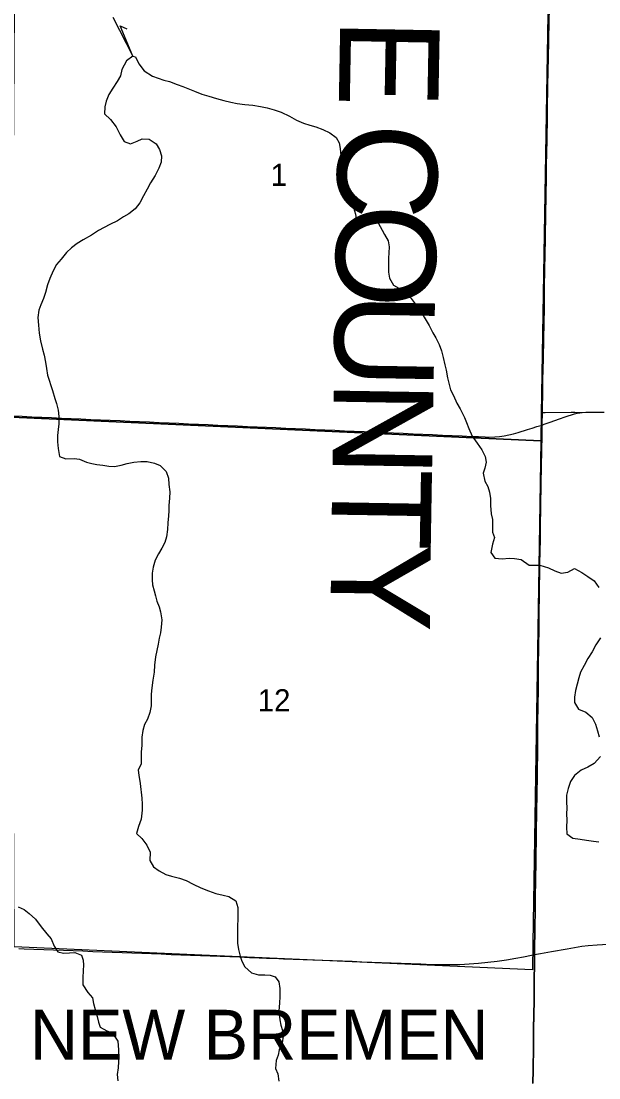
# Model space of a CAD drawing. Extents: x 0 to 34, y 0 to 22.
# Drawn here: x 6.802 to 7.901, y 17.185 to 19.194 of the extents above; entities that cross this region are included whole.
import ezdxf

# ---------------------------------------------------------------- set-up
doc = ezdxf.new("R2010")
doc.units = 0
for name, color, linetype in [('GM_X_Corporation', 7, 'Continuous'), ('GM_X_Corporation_Text', 7, 'Continuous'), ('GM_X_County_Road', 7, 'Continuous'), ('GM_X_County_Text', 7, 'Continuous'), ('GM_X_Minor_River', 7, 'Continuous'), ('GM_X_Section_Text', 7, 'Continuous'), ('GM_X_State_Route', 7, 'Continuous'), ('GM_X_Township_Road', 7, 'Continuous')]:
    doc.layers.add(name, color=color, linetype=linetype)

msp = doc.modelspace()

# ---------------------------------------------------------------- linework, layer by layer
at = {"layer": 'GM_X_Corporation'}
for points in [[(6.7967, 19.4154), (7.8071, 19.3973), (7.7914, 18.4475), (7.7907, 18.396), (6.7843, 18.4413), (6.7907, 19.4159)], [(7.7907, 18.396), (7.7756, 17.4406), (7.775, 17.3902), (6.7891, 17.4339), (6.7843, 18.4413)]]:
    msp.add_lwpolyline(points, close=True, dxfattribs=at)
for points in [[(7.8077, 19.2659), (7.8062, 19.1933), (7.8046, 19.1231), (7.8042, 19.1001), (7.8035, 19.0709), (7.803, 19.0255), (7.8028, 19.0087), (7.802, 18.9714), (7.8013, 18.9404), (7.8009, 18.923), (7.8007, 18.9013), (7.8002, 18.8578), (7.7997, 18.8304), (7.7991, 18.7813), (7.7984, 18.7484), (7.798, 18.7254), (7.7973, 18.6856), (7.7968, 18.6484), (7.7958, 18.5906), (7.7951, 18.552), (7.7941, 18.5123), (7.7937, 18.4937), (7.7933, 18.4506), (7.7929, 18.4266), (7.7926, 18.406), (7.792, 18.3768), (7.7914, 18.3476), (7.7909, 18.3147), (7.7902, 18.2712), (7.7895, 18.2321), (7.7892, 18.2091), (7.7888, 18.1855), (7.7885, 18.1637), (7.788, 18.1426), (7.7876, 18.1196), (7.7874, 18.0979), (7.7872, 18.0736), (7.787, 18.0631), (7.7867, 18.0339), (7.7864, 18.0109), (7.7863, 17.9991), (7.7859, 17.973), (7.7857, 17.9519), (7.7854, 17.9164), (7.7853, 17.8996), (7.7847, 17.8518), (7.7844, 17.8083), (7.784, 17.7648), (7.7832, 17.7188), (7.7828, 17.6971), (7.782, 17.648), (7.7814, 17.5977), (7.7808, 17.5616), (7.7801, 17.5281), (7.7799, 17.5113), (7.7793, 17.4635), (7.7789, 17.4324), (7.7787, 17.4202), (7.7785, 17.4094), (7.7785, 17.3964), (7.7783, 17.3759), (7.7781, 17.3547), (7.7779, 17.3342), (7.7775, 17.3032), (7.7771, 17.2808), (7.7767, 17.2454), (7.7759, 17.1994), (7.7755, 17.1752)], [(7.7755, 17.1752), (7.7759, 17.1994), (7.7767, 17.2454), (7.7771, 17.2808), (7.7775, 17.3032), (7.7779, 17.3342), (7.7781, 17.3547), (7.7783, 17.3759), (7.7785, 17.3964), (7.7785, 17.4094), (7.7787, 17.4202), (7.7789, 17.4324), (7.7793, 17.4635), (7.7799, 17.5113), (7.7801, 17.5281), (7.7808, 17.5616), (7.7814, 17.5977), (7.782, 17.648), (7.7828, 17.6971), (7.7832, 17.7188), (7.784, 17.7648), (7.7844, 17.8083), (7.7847, 17.8518), (7.7853, 17.8996), (7.7854, 17.9164), (7.7857, 17.9519), (7.7859, 17.973), (7.7863, 17.9991), (7.7864, 18.0109), (7.7867, 18.0339), (7.787, 18.0631), (7.7872, 18.0736), (7.7874, 18.0979), (7.7876, 18.1196), (7.788, 18.1426), (7.7885, 18.1637), (7.7888, 18.1855), (7.7892, 18.2091), (7.7895, 18.2321), (7.7902, 18.2712), (7.7909, 18.3147), (7.7914, 18.3476), (7.792, 18.3768), (7.7926, 18.406), (7.7929, 18.4266), (7.7933, 18.4506), (7.7937, 18.4937), (7.7941, 18.5123), (7.7951, 18.552), (7.7958, 18.5906), (7.7968, 18.6484), (7.7973, 18.6856), (7.798, 18.7254), (7.7984, 18.7484), (7.7991, 18.7813), (7.7997, 18.8304), (7.8002, 18.8578), (7.8007, 18.9013), (7.8009, 18.923), (7.8013, 18.9404), (7.802, 18.9714), (7.8028, 19.0087), (7.803, 19.0255), (7.8035, 19.0709), (7.8042, 19.1001), (7.8046, 19.1231), (7.8062, 19.1933), (7.8077, 19.2659)], [(7.7755, 17.1752), (7.7759, 17.1994), (7.7767, 17.2454), (7.7771, 17.2808), (7.7775, 17.3032), (7.7779, 17.3342), (7.7781, 17.3547), (7.7783, 17.3759), (7.7785, 17.3964), (7.7785, 17.4094), (7.7787, 17.4202), (7.7789, 17.4324), (7.7793, 17.4635), (7.7799, 17.5113), (7.7801, 17.5281), (7.7808, 17.5616), (7.7814, 17.5977), (7.782, 17.648), (7.7828, 17.6971), (7.7832, 17.7188), (7.784, 17.7648), (7.7844, 17.8083), (7.7847, 17.8518), (7.7853, 17.8996), (7.7854, 17.9164), (7.7857, 17.9519), (7.7859, 17.973), (7.7863, 17.9991), (7.7864, 18.0109), (7.7867, 18.0339), (7.787, 18.0631), (7.7872, 18.0736), (7.7874, 18.0979), (7.7876, 18.1196), (7.788, 18.1426), (7.7885, 18.1637), (7.7888, 18.1855), (7.7892, 18.2091), (7.7895, 18.2321), (7.7902, 18.2712), (7.7909, 18.3147), (7.7914, 18.3476), (7.792, 18.3768), (7.7926, 18.406), (7.7929, 18.4266), (7.7933, 18.4506), (7.7937, 18.4937), (7.7941, 18.5123), (7.7951, 18.552), (7.7958, 18.5906), (7.7968, 18.6484), (7.7973, 18.6856), (7.798, 18.7254), (7.7984, 18.7484), (7.7991, 18.7813), (7.7997, 18.8304), (7.8002, 18.8578), (7.8007, 18.9013), (7.8009, 18.923), (7.8013, 18.9404), (7.802, 18.9714), (7.8028, 19.0087), (7.803, 19.0255), (7.8035, 19.0709), (7.8042, 19.1001), (7.8046, 19.1231), (7.8062, 19.1933), (7.8077, 19.2659)], [(7.8077, 19.2659), (7.8062, 19.1933), (7.8046, 19.1231), (7.8042, 19.1001), (7.8035, 19.0709), (7.803, 19.0255), (7.8028, 19.0087), (7.802, 18.9714), (7.8013, 18.9404), (7.8009, 18.923), (7.8007, 18.9013), (7.8002, 18.8578), (7.7997, 18.8304), (7.7991, 18.7813), (7.7984, 18.7484), (7.798, 18.7254), (7.7973, 18.6856), (7.7968, 18.6484), (7.7958, 18.5906), (7.7951, 18.552), (7.7941, 18.5123), (7.7937, 18.4937), (7.7933, 18.4506), (7.7929, 18.4266), (7.7926, 18.406), (7.792, 18.3768), (7.7914, 18.3476), (7.7909, 18.3147), (7.7902, 18.2712), (7.7895, 18.2321), (7.7892, 18.2091), (7.7888, 18.1855), (7.7885, 18.1637), (7.788, 18.1426), (7.7876, 18.1196), (7.7874, 18.0979), (7.7872, 18.0736), (7.787, 18.0631), (7.7867, 18.0339), (7.7864, 18.0109), (7.7863, 17.9991), (7.7859, 17.973), (7.7857, 17.9519), (7.7854, 17.9164), (7.7853, 17.8996), (7.7847, 17.8518), (7.7844, 17.8083), (7.784, 17.7648), (7.7832, 17.7188), (7.7828, 17.6971), (7.782, 17.648), (7.7814, 17.5977), (7.7808, 17.5616), (7.7801, 17.5281), (7.7799, 17.5113), (7.7793, 17.4635), (7.7789, 17.4324), (7.7787, 17.4202), (7.7785, 17.4094), (7.7785, 17.3964), (7.7783, 17.3759), (7.7781, 17.3547), (7.7779, 17.3342), (7.7775, 17.3032), (7.7771, 17.2808), (7.7767, 17.2454), (7.7759, 17.1994), (7.7755, 17.1752)]]:
    msp.add_lwpolyline(points, dxfattribs=at)
at = {"layer": 'GM_X_County_Road'}
for p, q in [((7.7931, 18.4261), (7.7935, 18.45)), ((7.7788, 17.4008), (7.7789, 17.4196))]:
    msp.add_line(p, q, dxfattribs=at)
for points in [[(7.7935, 18.45), (7.794, 18.4931), (7.7944, 18.5117), (7.7948, 18.5304), (7.7951, 18.5409), (7.7953, 18.5515), (7.7957, 18.5701), (7.7959, 18.5801), (7.7961, 18.59), (7.7967, 18.6273), (7.7968, 18.6376), (7.797, 18.6478), (7.7973, 18.6664), (7.7974, 18.6758), (7.7975, 18.6851), (7.7982, 18.7249), (7.7987, 18.7478), (7.799, 18.7643), (7.7994, 18.7808), (7.7996, 18.7994), (7.7998, 18.8146), (7.8, 18.8299), (7.8004, 18.8572), (7.8009, 18.9007), (7.801, 18.9116), (7.8012, 18.9225), (7.8015, 18.9398), (7.8018, 18.9554), (7.8022, 18.9709), (7.8026, 18.9895), (7.8031, 19.0082), (7.8032, 19.025), (7.8036, 19.057), (7.8038, 19.0703), (7.8044, 19.0995), (7.8046, 19.111), (7.8048, 19.1225), (7.8057, 19.1598), (7.8061, 19.1762), (7.8064, 19.1927), (7.8076, 19.2477)], [(6.7856, 18.4436), (6.8043, 18.4427), (6.8229, 18.4419), (6.8415, 18.4411), (6.8601, 18.4402), (6.8788, 18.4394), (6.8974, 18.4386), (6.916, 18.4377), (6.9346, 18.4369), (6.9532, 18.4361), (6.9719, 18.4352), (6.9905, 18.4344), (7.0091, 18.4336), (7.0277, 18.4327), (7.0464, 18.4319), (7.065, 18.4311), (7.0836, 18.4302), (7.1022, 18.4294), (7.1208, 18.4286), (7.1395, 18.4277), (7.1581, 18.4269), (7.1767, 18.4261), (7.1953, 18.4252), (7.214, 18.4244), (7.2326, 18.4236), (7.2512, 18.4227), (7.2691, 18.4219), (7.287, 18.4211), (7.3057, 18.4203), (7.3243, 18.4195), (7.3429, 18.4187), (7.3615, 18.4178), (7.3801, 18.417), (7.3988, 18.4162), (7.4174, 18.4153), (7.436, 18.4145), (7.4546, 18.4137), (7.4733, 18.4129), (7.4919, 18.412), (7.5105, 18.4112), (7.5291, 18.4104), (7.5477, 18.4096), (7.5664, 18.4087), (7.585, 18.4079), (7.6036, 18.4071), (7.6222, 18.4063), (7.6409, 18.4055), (7.6595, 18.4046), (7.6722, 18.4041), (7.6849, 18.4035), (7.694, 18.4033), (7.703, 18.4036), (7.7121, 18.4043), (7.721, 18.4055), (7.7299, 18.4072), (7.7388, 18.4093), (7.7475, 18.4118), (7.7652, 18.4174), (7.7742, 18.4202), (7.7831, 18.4231), (7.7931, 18.4261)], [(7.7931, 18.4261), (7.7971, 18.4275), (7.8088, 18.4318), (7.8263, 18.4381), (7.8369, 18.4416), (7.8547, 18.4471), (7.86, 18.4485), (7.8648, 18.4494), (7.8661, 18.4496)], [(7.7935, 18.45), (7.7991, 18.4501), (7.8485, 18.4504), (7.8555, 18.4503), (7.8661, 18.4496)], [(7.8661, 18.4496), (7.8691, 18.4501), (7.8765, 18.4506), (7.8876, 18.4508), (7.9112, 18.4508)], [(7.7858, 17.9311), (7.7859, 17.9513), (7.7862, 17.9724), (7.7864, 17.9855), (7.7865, 17.9985), (7.7866, 18.0103), (7.7869, 18.0333), (7.7873, 18.0625), (7.7874, 18.0731), (7.7875, 18.0852), (7.7876, 18.0973), (7.7877, 18.1082), (7.7878, 18.1191), (7.7882, 18.1421), (7.7885, 18.1526), (7.7887, 18.1632), (7.7889, 18.1741), (7.7891, 18.1849), (7.7894, 18.2085), (7.7896, 18.22), (7.7898, 18.2315), (7.7902, 18.2604), (7.7904, 18.2707), (7.7907, 18.2893), (7.7909, 18.3017), (7.7911, 18.3142), (7.7917, 18.3471), (7.7928, 18.4055), (7.793, 18.4158), (7.7931, 18.4261)], [(7.7789, 17.4196), (7.7792, 17.4319), (7.7795, 17.4629), (7.7802, 17.5108), (7.7803, 17.5276), (7.7807, 17.5443), (7.781, 17.5611), (7.7816, 17.5971), (7.7819, 17.6158), (7.7822, 17.6475), (7.783, 17.6965), (7.7833, 17.7074), (7.7835, 17.7183), (7.7838, 17.7369), (7.7842, 17.7643), (7.7844, 17.7829), (7.7847, 17.8078), (7.7848, 17.8264), (7.7848, 17.8389), (7.7852, 17.8699), (7.7856, 17.8991), (7.7857, 17.9159), (7.7858, 17.9311)], [(7.7757, 17.1746), (7.7761, 17.1989), (7.7769, 17.2448), (7.7774, 17.2803), (7.7778, 17.3026), (7.7782, 17.3337), (7.7783, 17.3439), (7.7784, 17.3542), (7.7786, 17.3753), (7.7788, 17.3958), (7.7788, 17.4008)]]:
    msp.add_lwpolyline(points, dxfattribs=at)
at = {"layer": 'GM_X_Minor_River'}
for points in [[(6.9767, 19.2013), (7.0145, 19.1272), (6.9907, 19.185)], [(6.9907, 19.185), (7.0034, 19.179)], [(7.0145, 19.1272), (7.0026, 19.1187), (6.9938, 19.1018), (6.9912, 19.0901), (6.9852, 19.0793), (6.9765, 19.0666), (6.969, 19.0546), (6.9641, 19.0419), (6.9612, 19.0313), (6.9609, 19.018), (6.9723, 19.0067), (6.9833, 18.9928), (6.9905, 18.9778), (6.9985, 18.965), (7.0106, 18.9605), (7.0232, 18.9655), (7.0328, 18.9702), (7.0461, 18.9695), (7.0591, 18.9604), (7.0657, 18.9496), (7.0692, 18.9381), (7.0685, 18.926), (7.0644, 18.9143), (7.0572, 18.9005), (7.0484, 18.8863), (7.0417, 18.8743), (7.0353, 18.8616), (7.0281, 18.8485), (7.0191, 18.8373), (7.0071, 18.8278), (6.997, 18.8216), (6.9858, 18.8143), (6.9712, 18.8071), (6.9605, 18.8017), (6.9493, 18.7959), (6.9362, 18.7871), (6.9204, 18.7784), (6.9088, 18.7711), (6.898, 18.7627), (6.8883, 18.7542), (6.8785, 18.7416), (6.8698, 18.7312), (6.8635, 18.7192), (6.8566, 18.7049), (6.8525, 18.6929), (6.8487, 18.6782), (6.845, 18.6669), (6.8398, 18.6549), (6.8361, 18.6447), (6.8342, 18.6303), (6.8353, 18.6159), (6.8364, 18.6007), (6.8391, 18.5862), (6.8429, 18.5705), (6.846, 18.559), (6.8487, 18.5457), (6.8506, 18.5335), (6.8526, 18.5209), (6.8617, 18.4918), (6.8666, 18.4768), (6.8694, 18.4673), (6.8725, 18.4543), (6.8737, 18.4421), (6.8737, 18.4281), (6.873, 18.4178), (6.8716, 18.4061), (6.8716, 18.3939), (6.8728, 18.3817), (6.8755, 18.3661), (6.8875, 18.3616), (6.9031, 18.3627), (6.9133, 18.3609), (6.9268, 18.3556), (6.9366, 18.3531), (6.9464, 18.3513), (6.9574, 18.3495), (6.9691, 18.3481), (6.9801, 18.3474), (6.9923, 18.3501), (7.0038, 18.3532), (7.0167, 18.3552), (7.03, 18.3567), (7.0422, 18.3568), (7.0561, 18.3538), (7.067, 18.3489), (7.0781, 18.338), (7.0823, 18.325), (7.0835, 18.3128), (7.0854, 18.2994), (7.0847, 18.2869), (7.0832, 18.2729), (7.083, 18.263), (7.0824, 18.2536), (7.0812, 18.2399), (7.0806, 18.2278), (7.0787, 18.2134), (7.0753, 18.2025), (7.0701, 18.1923), (7.0634, 18.1811), (7.0574, 18.1691), (7.0533, 18.1559)], [(7.0145, 19.1272), (7.0198, 19.1258), (7.0259, 19.1127), (7.0366, 19.0992), (7.0523, 19.0893), (7.0628, 19.0856), (7.0737, 19.0819), (7.0842, 19.0789), (7.0989, 19.0732), (7.1098, 19.0695), (7.1323, 19.0606), (7.1462, 19.0549), (7.1594, 19.0515), (7.1741, 19.047), (7.188, 19.0432), (7.2012, 19.0398), (7.2129, 19.0376), (7.228, 19.0357), (7.2428, 19.0342), (7.2575, 19.0319), (7.2704, 19.0293), (7.2835, 19.0255), (7.2971, 19.0206), (7.3128, 19.013), (7.3259, 19.0058), (7.3394, 18.9998), (7.3514, 18.9964), (7.3631, 18.9927), (7.3759, 18.9878), (7.3894, 18.9814), (7.4017, 18.9727), (7.4071, 18.9627), (7.4091, 18.9516), (7.4102, 18.9383), (7.4101, 18.9201), (7.411, 18.9102), (7.4123, 18.8995), (7.4146, 18.8873), (7.4192, 18.8758), (7.4235, 18.8647), (7.4289, 18.8528), (7.4342, 18.8394), (7.438, 18.8267), (7.44, 18.8138), (7.4519, 18.8203), (7.4651, 18.8295), (7.4758, 18.8212), (7.4805, 18.8116), (7.4936, 18.7885), (7.5001, 18.7762), (7.5021, 18.7647), (7.5018, 18.7533), (7.5011, 18.7431), (7.5011, 18.7294), (7.5012, 18.7169), (7.5028, 18.7055), (7.5108, 18.692), (7.525, 18.6836), (7.5424, 18.6691), (7.5534, 18.654), (7.5637, 18.6408), (7.5687, 18.6312), (7.5786, 18.6154), (7.5854, 18.6015), (7.5909, 18.5919), (7.5974, 18.5792), (7.6016, 18.567), (7.6047, 18.5547), (7.6081, 18.5406), (7.6105, 18.5306), (7.6135, 18.5161), (7.6166, 18.5031), (7.619, 18.4932), (7.6244, 18.4821), (7.6309, 18.4678), (7.637, 18.457), (7.6457, 18.4405), (7.6496, 18.4309), (7.6539, 18.4194), (7.6603, 18.4052), (7.6695, 18.3916), (7.6786, 18.3789), (7.6851, 18.3662), (7.6867, 18.3555), (7.6842, 18.3442), (7.6809, 18.3344), (7.6843, 18.3195), (7.6897, 18.3091), (7.6929, 18.2987), (7.6952, 18.2865), (7.6952, 18.2728), (7.6963, 18.2572), (7.6991, 18.2462), (7.6991, 18.2329), (7.6988, 18.2222), (7.7024, 18.2123), (7.6986, 18.1998), (7.6959, 18.1839), (7.7032, 18.1727), (7.7173, 18.172), (7.7302, 18.1732)], [(7.7302, 18.1732), (7.7404, 18.1721), (7.7533, 18.1703), (7.7685, 18.1596), (7.7888, 18.16)], [(7.0533, 18.1559), (7.0518, 18.1446), (7.0515, 18.132), (7.052, 18.1225), (7.0551, 18.1111), (7.0579, 18.1011), (7.0603, 18.0915), (7.0646, 18.0804), (7.0674, 18.0708), (7.0696, 18.0556), (7.0689, 18.0415), (7.0671, 18.0313), (7.0649, 18.0208), (7.0628, 18.0094), (7.0602, 17.9977), (7.0576, 17.9856), (7.0557, 17.9697), (7.0553, 17.956), (7.053, 17.9409), (7.0508, 17.9265), (7.0497, 17.9144), (7.0494, 17.9037), (7.0495, 17.8923), (7.0469, 17.8795), (7.0424, 17.8667), (7.0368, 17.8566), (7.0339, 17.8452), (7.032, 17.8324), (7.0316, 17.8172), (7.0309, 17.8039), (7.0306, 17.7921), (7.0307, 17.7818), (7.0251, 17.7698), (7.0264, 17.7603), (7.0286, 17.7443), (7.0317, 17.7168), (7.0326, 17.7054), (7.0323, 17.694), (7.0307, 17.6769), (7.0254, 17.6626), (7.022, 17.6494), (7.0317, 17.64), (7.0416, 17.6272), (7.0477, 17.6141), (7.0469, 17.5982), (7.0538, 17.5862), (7.0646, 17.5783), (7.0777, 17.5719), (7.0882, 17.5686), (7.1033, 17.5648), (7.1161, 17.5603), (7.1296, 17.5534), (7.1438, 17.5462), (7.1585, 17.5405), (7.1728, 17.5356), (7.1863, 17.5322), (7.1973, 17.5296), (7.2107, 17.5213), (7.2146, 17.509), (7.2146, 17.495), (7.2138, 17.4657), (7.2139, 17.452), (7.214, 17.441), (7.2156, 17.4288), (7.219, 17.4165), (7.2218, 17.4069), (7.2276, 17.3962), (7.2402, 17.3844), (7.2538, 17.3806), (7.2659, 17.3811), (7.2758, 17.3805), (7.2856, 17.3772), (7.2925, 17.3675), (7.2945, 17.3549), (7.2945, 17.3397), (7.2934, 17.3268), (7.2926, 17.3123), (7.2945, 17.2952), (7.2961, 17.2853), (7.2993, 17.2753), (7.3009, 17.2642), (7.299, 17.2517), (7.293, 17.2382), (7.2912, 17.228), (7.2872, 17.2182), (7.286, 17.2026), (7.2907, 17.1926), (7.2926, 17.1789)], [(7.7888, 18.16), (7.8053, 18.1543), (7.8174, 18.1488), (7.8295, 18.1447), (7.8421, 18.1464), (7.8549, 18.1534), (7.8685, 18.1459), (7.8802, 18.1384), (7.8922, 18.1298), (7.9012, 18.1175)], [(7.9044, 18.0215), (7.8953, 18.0083), (7.8882, 17.9948), (7.88, 17.982), (7.8729, 17.9692), (7.8662, 17.956), (7.8633, 17.9457), (7.86, 17.9336), (7.8567, 17.9211), (7.855, 17.9086), (7.8548, 17.8983), (7.8626, 17.886), (7.8766, 17.8804), (7.8886, 17.8703), (7.8949, 17.8572), (7.8985, 17.8446), (7.9017, 17.8335)], [(7.9045, 17.7957), (7.8924, 17.7826), (7.88, 17.7756), (7.8677, 17.7701), (7.855, 17.7601), (7.8471, 17.7481), (7.8427, 17.7348), (7.8398, 17.7223), (7.8395, 17.7097), (7.8405, 17.6979), (7.8395, 17.6869), (7.8404, 17.6751), (7.8398, 17.6614), (7.84, 17.6492), (7.8516, 17.6406), (7.8654, 17.6388), (7.8779, 17.637), (7.8912, 17.6353), (7.9011, 17.6339)], [(6.7969, 17.5104), (6.8078, 17.5048), (6.8178, 17.4973), (6.8293, 17.4868), (6.8407, 17.4724), (6.8514, 17.4588), (6.8591, 17.4491), (6.8648, 17.4356), (6.8721, 17.4244), (6.8827, 17.4222), (6.8945, 17.4227), (6.9043, 17.4232), (6.9171, 17.4183), (6.9203, 17.4087), (6.9208, 17.3992), (6.9201, 17.3889), (6.9194, 17.3749), (6.9198, 17.362), (6.9293, 17.3476), (6.9382, 17.3371), (6.9402, 17.3261), (6.9429, 17.315), (6.9467, 17.3016), (6.9495, 17.2912), (6.9523, 17.2813), (6.9654, 17.2745), (6.9756, 17.2708), (6.9861, 17.2545), (6.9876, 17.2381), (6.9877, 17.2271), (6.9874, 17.2161), (6.9867, 17.204), (6.9849, 17.1915), (6.9865, 17.1792)]]:
    msp.add_lwpolyline(points, dxfattribs=at)
at = {"layer": 'GM_X_State_Route'}
for points in [[(7.7789, 17.4196), (7.7899, 17.4215), (7.8113, 17.4253), (7.8406, 17.4306), (7.8688, 17.4351), (7.8805, 17.4365), (7.8978, 17.438), (7.9183, 17.4393)], [(6.7976, 17.4309), (6.8081, 17.4305), (6.8267, 17.4298), (6.8453, 17.4291), (6.8639, 17.4283), (6.8826, 17.4276), (6.9012, 17.4269), (6.9198, 17.4262), (6.9385, 17.4255), (6.9571, 17.4248), (6.9757, 17.4241), (6.9943, 17.4233), (7.013, 17.4226), (7.0316, 17.4219), (7.0502, 17.4212), (7.0689, 17.4205), (7.0875, 17.4198), (7.1061, 17.4191), (7.1247, 17.4183), (7.1434, 17.4176), (7.162, 17.4169), (7.1806, 17.4162), (7.1993, 17.4155), (7.2179, 17.4148), (7.2365, 17.4141), (7.2551, 17.4134), (7.269, 17.4128), (7.2828, 17.4123), (7.3014, 17.4116), (7.32, 17.4109), (7.3387, 17.4102), (7.3573, 17.4095), (7.3759, 17.4087), (7.3946, 17.408), (7.4132, 17.4073), (7.4318, 17.4066), (7.4504, 17.4059), (7.4691, 17.4052), (7.4877, 17.4045), (7.5063, 17.4038), (7.525, 17.403), (7.5436, 17.4023), (7.5622, 17.4016), (7.5725, 17.4012), (7.5828, 17.4008), (7.6006, 17.4004), (7.6185, 17.4006), (7.6364, 17.4008), (7.6543, 17.4016), (7.6721, 17.4029), (7.6899, 17.4047), (7.7077, 17.4069), (7.7254, 17.4095), (7.743, 17.4125), (7.7578, 17.4153), (7.7727, 17.4181), (7.7789, 17.4196)]]:
    msp.add_lwpolyline(points, dxfattribs=at)
at = {"layer": 'GM_X_Township_Road'}
for p, q in [((7.7931, 18.4261), (7.7935, 18.45)), ((7.7788, 17.4008), (7.7789, 17.4196))]:
    msp.add_line(p, q, dxfattribs=at)
for points in [[(7.7935, 18.45), (7.794, 18.4931), (7.7944, 18.5117), (7.7948, 18.5304), (7.7951, 18.5409), (7.7953, 18.5515), (7.7957, 18.5701), (7.7959, 18.5801), (7.7961, 18.59), (7.7967, 18.6273), (7.7968, 18.6376), (7.797, 18.6478), (7.7973, 18.6664), (7.7974, 18.6758), (7.7975, 18.6851), (7.7982, 18.7249), (7.7987, 18.7478), (7.799, 18.7643), (7.7994, 18.7808), (7.7996, 18.7994), (7.7998, 18.8146), (7.8, 18.8299), (7.8004, 18.8572), (7.8009, 18.9007), (7.801, 18.9116), (7.8012, 18.9225), (7.8015, 18.9398), (7.8018, 18.9554), (7.8022, 18.9709), (7.8026, 18.9895), (7.8031, 19.0082), (7.8032, 19.025), (7.8036, 19.057), (7.8038, 19.0703), (7.8044, 19.0995), (7.8046, 19.111), (7.8048, 19.1225), (7.8057, 19.1598), (7.8061, 19.1762), (7.8064, 19.1927), (7.8076, 19.2477)], [(7.7858, 17.9311), (7.7859, 17.9513), (7.7862, 17.9724), (7.7864, 17.9855), (7.7865, 17.9985), (7.7866, 18.0103), (7.7869, 18.0333), (7.7873, 18.0625), (7.7874, 18.0731), (7.7875, 18.0852), (7.7876, 18.0973), (7.7877, 18.1082), (7.7878, 18.1191), (7.7882, 18.1421), (7.7885, 18.1526), (7.7887, 18.1632), (7.7889, 18.1741), (7.7891, 18.1849), (7.7894, 18.2085), (7.7896, 18.22), (7.7898, 18.2315), (7.7902, 18.2604), (7.7904, 18.2707), (7.7907, 18.2893), (7.7909, 18.3017), (7.7911, 18.3142), (7.7917, 18.3471), (7.7928, 18.4055), (7.793, 18.4158), (7.7931, 18.4261)], [(7.7789, 17.4196), (7.7792, 17.4319), (7.7795, 17.4629), (7.7802, 17.5108), (7.7803, 17.5276), (7.7807, 17.5443), (7.781, 17.5611), (7.7816, 17.5971), (7.7819, 17.6158), (7.7822, 17.6475), (7.783, 17.6965), (7.7833, 17.7074), (7.7835, 17.7183), (7.7838, 17.7369), (7.7842, 17.7643), (7.7844, 17.7829), (7.7847, 17.8078), (7.7848, 17.8264), (7.7848, 17.8389), (7.7852, 17.8699), (7.7856, 17.8991), (7.7857, 17.9159), (7.7858, 17.9311)], [(7.7757, 17.1746), (7.7761, 17.1989), (7.7769, 17.2448), (7.7774, 17.2803), (7.7778, 17.3026), (7.7782, 17.3337), (7.7783, 17.3439), (7.7784, 17.3542), (7.7786, 17.3753), (7.7788, 17.3958), (7.7788, 17.4008)]]:
    msp.add_lwpolyline(points, dxfattribs=at)

# ---------------------------------------------------------------- texts
at = {"layer": 'GM_X_Corporation_Text'}
msp.add_text('NEW BREMEN', height=0.0947, rotation=0, dxfattribs=at).set_placement((6.8189, 17.2197))
at = {"layer": 'GM_X_County_Text'}
for s, rotation, p in [('E', 268.9585, (7.4094, 19.2007)), ('C', 269.0093, (7.4058, 19.0015)), ('O', 269.0137, (7.4031, 18.8474)), ('U', 269.018, (7.4003, 18.6799)), ('N', 269.0289, (7.3974, 18.5124)), ('T', 269.0408, (7.3945, 18.3449)), ('Y', 269.4063, (7.3922, 18.203))]:
    msp.add_text(s, height=0.1894, rotation=rotation, dxfattribs=at).set_placement(p)
at = {"layer": 'GM_X_Section_Text'}
for s, height, p in [('1', 0.0419, (7.2768, 18.8808)), ('12', 0.04186, (7.2522, 17.882))]:
    msp.add_text(s, height=height, rotation=0, dxfattribs=at).set_placement(p)

doc.saveas('drawing.dxf')
